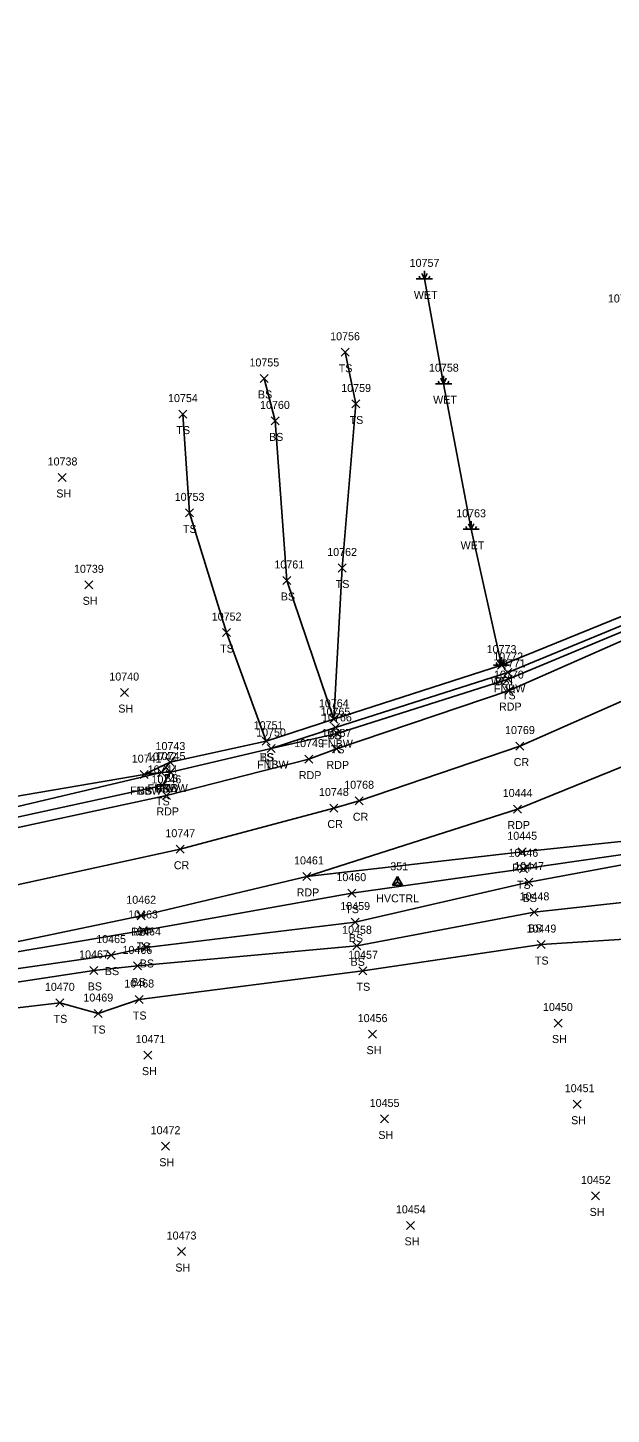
# Model space of a CAD drawing. Extents: x 1475671 to 1477951, y 592661 to 593821.
# Drawn here: x 1476339 to 1476484.8, y 592897.6 to 593244.1 of the extents above; entities that cross this region are included whole.
import ezdxf

# ---------------------------------------------------------------- set-up
doc = ezdxf.new("R2010")
doc.units = 0
for name, color, linetype in [('C_A', 7, 'Continuous'), ('C_I', 7, 'Continuous'), ('CPSM', 7, 'Continuous'), ('L_A', 7, 'Continuous'), ('L_I', 7, 'Continuous'), ('L_TIC', 7, 'Continuous'), ('LELB', 7, 'Continuous'), ('LFNC', 7, 'Continuous'), ('LWET', 7, 'Continuous'), ('P_A', 7, 'Continuous'), ('P_I', 7, 'Continuous'), ('P_TIC', 7, 'Continuous'), ('PET', 7, 'Continuous'), ('PRC', 7, 'Continuous')]:
    doc.layers.add(name, color=color, linetype=linetype)

msp = doc.modelspace()

# ---------------------------------------------------------------- linework, layer by layer
at = {"layer": 'CPSM'}
for p, q in [((1476430.13, 593029.85), (1476431.38, 593032.02)), ((1476432.63, 593029.85), (1476431.38, 593032.02)), ((1476431.38, 593030.57), (1476431.38, 593032.02)), ((1476430.13, 593029.85), (1476431.38, 593030.57)), ((1476430.13, 593029.85), (1476432.63, 593029.85)), ((1476431.38, 593030.57), (1476431.38, 593030.57)), ((1476431.38, 593030.57), (1476432.63, 593029.85))]:
    msp.add_line(p, q, dxfattribs=at)
at = {"layer": 'L_TIC'}
for points in [[(1476417.29, 593162.03), (1476419.29, 593164.03)], [(1476419.29, 593162.03), (1476417.29, 593164.03)], [(1476397.07, 593155.49), (1476399.07, 593157.49)], [(1476399.07, 593155.49), (1476397.07, 593157.49)], [(1476420.01, 593149.11), (1476422.01, 593151.11)], [(1476422.01, 593149.11), (1476420.01, 593151.11)], [(1476376.72, 593146.58), (1476378.72, 593148.58)], [(1476378.72, 593146.58), (1476376.72, 593148.58)], [(1476399.84, 593144.88), (1476401.84, 593146.88)], [(1476401.84, 593144.88), (1476399.84, 593146.88)], [(1476346.63, 593130.74), (1476348.63, 593132.74)], [(1476348.63, 593130.74), (1476346.63, 593132.74)], [(1476378.38, 593121.89), (1476380.38, 593123.89)], [(1476380.38, 593121.89), (1476378.38, 593123.89)], [(1476416.54, 593108.12), (1476418.54, 593110.12)], [(1476418.54, 593108.12), (1476416.54, 593110.12)], [(1476353.22, 593103.92), (1476355.22, 593105.92)], [(1476355.22, 593103.92), (1476353.22, 593105.92)], [(1476402.77, 593105), (1476404.77, 593107)], [(1476404.77, 593105), (1476402.77, 593107)], [(1476387.64, 593091.98), (1476389.64, 593093.98)], [(1476389.64, 593091.98), (1476387.64, 593093.98)], [(1476456.34, 593083.84), (1476458.34, 593085.84)], [(1476458.34, 593083.84), (1476456.34, 593085.84)], [(1476457.99, 593082.01), (1476459.99, 593084.01)], [(1476459.99, 593082.01), (1476457.99, 593084.01)], [(1476458.07, 593080.3), (1476460.07, 593082.3)], [(1476460.07, 593080.3), (1476458.07, 593082.3)], [(1476362.14, 593076.99), (1476364.14, 593078.99)], [(1476364.14, 593076.99), (1476362.14, 593078.99)], [(1476414.47, 593070.31), (1476416.47, 593072.31)], [(1476416.47, 593070.31), (1476414.47, 593072.31)], [(1476414.47, 593070.31), (1476416.47, 593072.31)], [(1476416.47, 593070.31), (1476414.47, 593072.31)], [(1476414.47, 593070.31), (1476416.47, 593072.31)], [(1476416.47, 593070.31), (1476414.47, 593072.31)], [(1476414.89, 593068.22), (1476416.89, 593070.22)], [(1476416.89, 593068.22), (1476414.89, 593070.22)], [(1476397.56, 593064.83), (1476399.56, 593066.83)], [(1476399.56, 593064.83), (1476397.56, 593066.83)], [(1476397.56, 593064.83), (1476399.56, 593066.83)], [(1476399.56, 593064.83), (1476397.56, 593066.83)], [(1476415.3, 593066.79), (1476417.3, 593068.79)], [(1476417.3, 593066.79), (1476415.3, 593068.79)], [(1476398.83, 593063.01), (1476400.83, 593065.01)], [(1476400.83, 593063.01), (1476398.83, 593065.01)], [(1476398.83, 593063.01), (1476400.83, 593065.01)], [(1476400.83, 593063.01), (1476398.83, 593065.01)], [(1476371.45, 593057.02), (1476373.45, 593059.02)], [(1476373.45, 593057.02), (1476371.45, 593059.02)], [(1476371.45, 593057.02), (1476373.45, 593059.02)], [(1476373.45, 593057.02), (1476371.45, 593059.02)], [(1476373.59, 593059.62), (1476375.59, 593061.62)], [(1476375.59, 593059.62), (1476373.59, 593061.62)], [(1476373.59, 593059.62), (1476375.59, 593061.62)], [(1476375.59, 593059.62), (1476373.59, 593061.62)], [(1476373.63, 593057.12), (1476375.63, 593059.12)], [(1476375.63, 593057.12), (1476373.63, 593059.12)], [(1476373.63, 593057.12), (1476375.63, 593059.12)], [(1476375.63, 593057.12), (1476373.63, 593059.12)], [(1476367.09, 593056.49), (1476369.09, 593058.49)], [(1476369.09, 593056.49), (1476367.09, 593058.49)], [(1476367.09, 593056.49), (1476369.09, 593058.49)], [(1476369.09, 593056.49), (1476367.09, 593058.49)], [(1476371.64, 593053.79), (1476373.64, 593055.79)], [(1476373.64, 593053.79), (1476371.64, 593055.79)], [(1476461.84, 593032.95), (1476463.84, 593034.95)], [(1476463.84, 593032.95), (1476461.84, 593034.95)], [(1476463.22, 593029.64), (1476465.22, 593031.64)], [(1476465.22, 593029.64), (1476463.22, 593031.64)], [(1476418.94, 593026.86), (1476420.94, 593028.86)], [(1476420.94, 593026.86), (1476418.94, 593028.86)], [(1476419.77, 593019.64), (1476421.77, 593021.64)], [(1476421.77, 593019.64), (1476419.77, 593021.64)], [(1476464.56, 593022.07), (1476466.56, 593024.07)], [(1476466.56, 593022.07), (1476464.56, 593024.07)], [(1476366.81, 593017.54), (1476368.81, 593019.54)], [(1476368.81, 593017.54), (1476366.81, 593019.54)], [(1476367.55, 593013.29), (1476369.55, 593015.29)], [(1476369.55, 593013.29), (1476367.55, 593015.29)], [(1476420.22, 593013.7), (1476422.22, 593015.7)], [(1476422.22, 593013.7), (1476420.22, 593015.7)], [(1476466.31, 593014.01), (1476468.31, 593016.01)], [(1476468.31, 593014.01), (1476466.31, 593016.01)], [(1476358.82, 593011.38), (1476360.82, 593013.38)], [(1476360.82, 593011.38), (1476358.82, 593013.38)], [(1476365.44, 593008.67), (1476367.44, 593010.67)], [(1476367.44, 593008.67), (1476365.44, 593010.67)], [(1476354.54, 593007.55), (1476356.54, 593009.55)], [(1476356.54, 593007.55), (1476354.54, 593009.55)], [(1476421.73, 593007.46), (1476423.73, 593009.46)], [(1476423.73, 593007.46), (1476421.73, 593009.46)], [(1476346.04, 592999.45), (1476348.04, 593001.45)], [(1476348.04, 592999.45), (1476346.04, 593001.45)], [(1476365.85, 593000.28), (1476367.85, 593002.28)], [(1476367.85, 593000.28), (1476365.85, 593002.28)], [(1476355.63, 592996.77), (1476357.63, 592998.77)], [(1476357.63, 592996.77), (1476355.63, 592998.77)], [(1476424.16, 592991.63), (1476426.16, 592993.63)], [(1476426.16, 592991.63), (1476424.16, 592993.63)], [(1476470.49, 592994.41), (1476472.49, 592996.41)], [(1476472.49, 592994.41), (1476470.49, 592996.41)], [(1476368.04, 592986.39), (1476370.04, 592988.39)], [(1476370.04, 592986.39), (1476368.04, 592988.39)], [(1476475.28, 592974.12), (1476477.28, 592976.12)], [(1476477.28, 592974.12), (1476475.28, 592976.12)], [(1476427.11, 592970.43), (1476429.11, 592972.43)], [(1476429.11, 592970.43), (1476427.11, 592972.43)], [(1476372.38, 592963.62), (1476374.38, 592965.62)], [(1476374.38, 592963.62), (1476372.38, 592965.62)], [(1476479.9, 592951.2), (1476481.9, 592953.2)], [(1476481.9, 592951.2), (1476479.9, 592953.2)], [(1476433.66, 592943.84), (1476435.66, 592945.84)], [(1476435.66, 592943.84), (1476433.66, 592945.84)], [(1476376.38, 592937.3), (1476378.38, 592939.3)], [(1476378.38, 592937.3), (1476376.38, 592939.3)]]:
    msp.add_lwpolyline(points, dxfattribs=at)
at = {"layer": 'LELB'}
for points in [[(1476418.29, 593163.03), (1476421.01, 593150.11), (1476417.54, 593109.12), (1476415.47, 593071.31)], [(1476398.07, 593156.49), (1476400.84, 593145.88), (1476403.77, 593106), (1476415.47, 593071.31)], [(1476398.56, 593065.83), (1476388.64, 593092.98), (1476379.38, 593122.89), (1476377.72, 593147.58)], [(1476399.83, 593064.01), (1476416.3, 593067.79), (1476459.07, 593081.3), (1476500.05, 593098.39), (1476506.4, 593103.47)], [(1475681.97, 592926.29), (1475693.99, 592930.92), (1475717.71, 592935.95), (1475764.49, 592948.74), (1475792.84, 592955.38), (1475826.76, 592965.2), (1475839.14, 592967.57), (1475847.44, 592968.45), (1475896, 592975.83), (1475948.75, 592985.5), (1475992.67, 592993.57), (1476057.44, 593003.96), (1476113.1, 593013.57), (1476163.64, 593021.28), (1476215.98, 593029.82), (1476272.69, 593037.85), (1476322.72, 593046.24), (1476372.45, 593058.02), (1476374.59, 593060.62), (1476398.56, 593065.83), (1476415.47, 593071.31), (1476457.34, 593084.84)], [(1476656.72, 593061.12), (1476648.18, 593059.88), (1476630.02, 593056.59), (1476594.66, 593048.99), (1476557.23, 593045.74), (1476521.08, 593042.35), (1476462.84, 593033.95), (1476419.94, 593027.86), (1476367.81, 593018.54), (1476319.05, 593010.3), (1476266.9, 593001.04), (1476164.01, 592984.31)], [(1476368.09, 593057.49), (1476374.59, 593060.62)], [(1475681.68, 592929.89), (1475693.99, 592930.92), (1475717.95, 592934.41), (1475766.45, 592946.03), (1475793.6, 592952.64), (1475827.75, 592961.96), (1475839.66, 592963.32), (1475897.61, 592972.89), (1475949.51, 592982.21), (1475996.32, 592990.67), (1476057.58, 593001.03), (1476113.5, 593010.46), (1476164.33, 593018.66), (1476216.45, 593027.16), (1476273.17, 593035.57), (1476322.97, 593043.9), (1476372.64, 593054.79), (1476374.63, 593058.12)], [(1476521.14, 593041.18), (1476464.22, 593030.64), (1476420.77, 593020.64), (1476368.55, 593014.29), (1476359.82, 593012.38), (1476319.88, 593006.6), (1476267.05, 592998.99), (1476216.33, 592991.85), (1476164.01, 592984.31), (1476119.67, 592976.43), (1476101.12, 592973.12), (1476050.25, 592964.51), (1475994.64, 592956.24), (1475948.73, 592947.98), (1475899.49, 592939.5), (1475855.9, 592931.1), (1475802.57, 592920.15), (1475791.75, 592916.74), (1475792.51, 592914.78)], [(1476534.65, 593028.56), (1476525.69, 593019.5), (1476511.54, 593017.85), (1476467.31, 593015.01), (1476422.73, 593008.46), (1476366.85, 593001.28), (1476356.63, 592997.77), (1476347.04, 593000.45), (1476320.8, 592997.35), (1476267.98, 592990.13), (1476216.9, 592984.46), (1476165.76, 592976.73), (1476117.9, 592968.73), (1476100.74, 592966.91), (1476051.72, 592958.25), (1475996.01, 592950.36), (1475948.39, 592939), (1475900.82, 592931.75), (1475857.92, 592923.91), (1475803.59, 592912.34), (1475790.59, 592904.71)], [(1476511.04, 593028.14), (1476465.56, 593023.07), (1476421.22, 593014.7), (1476366.44, 593009.67), (1476355.54, 593008.55), (1476320.37, 593003.18), (1476267.54, 592995.9), (1476216.93, 592987.92), (1476164.84, 592980.53), (1476118, 592971.7), (1476100.88, 592970.48), (1476050.95, 592961.21), (1475995.34, 592954.17), (1475949.24, 592944.73), (1475901.01, 592937.79), (1475856.17, 592929.37), (1475802.39, 592917.73), (1475792.51, 592914.78)]]:
    msp.add_lwpolyline(points, dxfattribs=at)
at = {"layer": 'LFNC'}
msp.add_lwpolyline([(1475680.63, 592937.28), (1475715.61, 592943.34), (1475763.84, 592955.14), (1475791.92, 592961.08), (1475824.89, 592967.76), (1475839.13, 592970.46), (1475847.47, 592971.97), (1475895.02, 592980.45), (1475948.31, 592989.25), (1475993.78, 592996.67), (1476056.99, 593006.94), (1476113.81, 593016.03), (1476164.23, 593025.08), (1476215.07, 593032.59), (1476272.43, 593042.08), (1476322.23, 593049.67), (1476368.09, 593057.49), (1476372.45, 593058.02), (1476374.63, 593058.12), (1476399.83, 593064.01), (1476415.89, 593069.22), (1476458.99, 593083.01), (1476499.73, 593099.84)], dxfattribs=at)
at = {"layer": 'LWET'}
for p, q in [((1476440.09, 593181.37), (1476436.09, 593181.37)), ((1476437.09, 593181.37), (1476436.76, 593182.03)), ((1476438.09, 593181.37), (1476437.43, 593182.7)), ((1476438.09, 593181.37), (1476438.09, 593183.37)), ((1476438.09, 593181.37), (1476438.76, 593182.7)), ((1476439.09, 593181.37), (1476439.43, 593182.03)), ((1476442.92, 593155.18), (1476442.25, 593156.52)), ((1476442.92, 593155.18), (1476442.92, 593157.18)), ((1476442.92, 593155.18), (1476443.58, 593156.52)), ((1476444.92, 593155.18), (1476440.92, 593155.18)), ((1476441.92, 593155.18), (1476441.58, 593155.85)), ((1476443.92, 593155.18), (1476444.25, 593155.85)), ((1476451.77, 593118.79), (1476447.77, 593118.79)), ((1476448.77, 593118.79), (1476448.44, 593119.46)), ((1476449.77, 593118.79), (1476449.11, 593120.13)), ((1476449.77, 593118.79), (1476449.77, 593120.79)), ((1476449.77, 593118.79), (1476450.44, 593120.13)), ((1476450.77, 593118.79), (1476451.11, 593119.46)), ((1476457.34, 593084.84), (1476457.34, 593086.84)), ((1476459.34, 593084.84), (1476455.34, 593084.84)), ((1476456.34, 593084.84), (1476456, 593085.5)), ((1476457.34, 593084.84), (1476456.67, 593086.17)), ((1476457.34, 593084.84), (1476458, 593086.17)), ((1476458.34, 593084.84), (1476458.67, 593085.5))]:
    msp.add_line(p, q, dxfattribs=at)
msp.add_lwpolyline([(1476438.09, 593181.37), (1476442.92, 593155.18), (1476449.77, 593118.79), (1476457.34, 593084.84), (1476498.59, 593101.6), (1476489.99, 593126.57), (1476487.68, 593172.48), (1476489.56, 593212.3), (1476496.66, 593244.14)], dxfattribs=at)
at = {"layer": 'P_TIC'}
for points in [[(1476458.25, 593077.48), (1476460.25, 593079.48)], [(1476460.25, 593077.48), (1476458.25, 593079.48)], [(1476415.16, 593062.9), (1476417.16, 593064.9)], [(1476417.16, 593062.9), (1476415.16, 593064.9)], [(1476460.98, 593063.62), (1476462.98, 593065.62)], [(1476462.98, 593063.62), (1476460.98, 593065.62)], [(1476408.24, 593060.35), (1476410.24, 593062.35)], [(1476410.24, 593060.35), (1476408.24, 593062.35)], [(1476372.65, 593051.29), (1476374.65, 593053.29)], [(1476374.65, 593051.29), (1476372.65, 593053.29)], [(1476414.44, 593048.14), (1476416.44, 593050.14)], [(1476416.44, 593048.14), (1476414.44, 593050.14)], [(1476420.8, 593049.95), (1476422.8, 593051.95)], [(1476422.8, 593049.95), (1476420.8, 593051.95)], [(1476460.35, 593047.89), (1476462.35, 593049.89)], [(1476462.35, 593047.89), (1476460.35, 593049.89)], [(1476376.06, 593037.84), (1476378.06, 593039.84)], [(1476378.06, 593037.84), (1476376.06, 593039.84)], [(1476461.5, 593037.2), (1476463.5, 593039.2)], [(1476463.5, 593037.2), (1476461.5, 593039.2)], [(1476407.69, 593031.05), (1476409.69, 593033.05)], [(1476409.69, 593031.05), (1476407.69, 593033.05)], [(1476407.69, 593031.05), (1476409.69, 593033.05)], [(1476409.69, 593031.05), (1476407.69, 593033.05)], [(1476366.34, 593021.2), (1476368.34, 593023.2)], [(1476368.34, 593021.2), (1476366.34, 593023.2)]]:
    msp.add_lwpolyline(points, dxfattribs=at)
at = {"layer": 'PET'}
for points in [[(1475682.06, 592924.71), (1475717.58, 592931.68), (1475766.32, 592943.31), (1475794.98, 592949.79), (1475825.77, 592956.33), (1475844.1, 592960.26), (1475899.54, 592970.95), (1475949.72, 592980.21), (1475996.45, 592988.43), (1476057.84, 592998.4), (1476110.05, 593006.96), (1476164.18, 593015.73), (1476216.75, 593023.76), (1476273.83, 593032.32), (1476323.32, 593041.42), (1476373.65, 593052.29), (1476409.24, 593061.35), (1476416.16, 593063.9), (1476459.25, 593078.48), (1476508.39, 593100.17)], [(1476493.61, 593061.9), (1476461.35, 593048.89), (1476408.69, 593032.05)], [(1476521.33, 593044.37), (1476462.5, 593038.2), (1476408.69, 593032.05), (1476367.34, 593022.2), (1476318.64, 593012.07), (1476266.69, 593003.36), (1476216.58, 592995.35), (1476163.86, 592987.33), (1476119.65, 592980.05), (1476101.05, 592977.22), (1476048.95, 592968.83), (1475997.04, 592960.32), (1475947.8, 592951.63), (1475898.72, 592942.8), (1475855.26, 592933.74), (1475801.94, 592923.33), (1475788.88, 592919.68), (1475771.17, 592916.5), (1475722.69, 592905.51), (1475685.82, 592897.63)]]:
    msp.add_lwpolyline(points, dxfattribs=at)
at = {"layer": 'PRC'}
msp.add_lwpolyline([(1475683.62, 592911.01), (1475719.65, 592918.7), (1475759.33, 592927.39), (1475790.86, 592934.39), (1475834.03, 592943.87), (1475901.67, 592957.18), (1475953.57, 592967.02), (1476000.12, 592975.16), (1476059.54, 592984.65), (1476113.3, 592993.58), (1476166.39, 593001.74), (1476218.93, 593009.6), (1476277, 593018.86), (1476325.59, 593027.6), (1476377.06, 593038.84), (1476415.44, 593049.14), (1476421.8, 593050.95), (1476461.98, 593064.62), (1476520.7, 593090.52)], dxfattribs=at)

# ---------------------------------------------------------------- texts
at = {"layer": 'C_A'}
msp.add_text('HVCTRL', height=2, dxfattribs=at).set_placement((1476426.07, 593025.57))
at = {"layer": 'C_I'}
msp.add_text('351', height=2, dxfattribs=at).set_placement((1476429.58, 593033.57))
at = {"layer": 'L_A'}
for s, p in [('WET', (1476435.47, 593176.37)), ('TS', (1476416.7, 593158.03)), ('BS', (1476396.51, 593151.49)), ('WET', (1476440.29, 593150.18)), ('TS', (1476419.42, 593145.11)), ('TS', (1476376.13, 593142.58)), ('BS', (1476399.28, 593140.88)), ('SH', (1476346.12, 593126.74)), ('TS', (1476377.79, 593117.89)), ('WET', (1476447.15, 593113.79)), ('TS', (1476415.95, 593104.12)), ('SH', (1476352.71, 593099.92)), ('BS', (1476402.22, 593101)), ('TS', (1476387.05, 593087.98)), ('WET', (1476454.71, 593079.84)), ('FNBW', (1476455.47, 593078.01)), ('BS', (1476455.78, 593079.84)), ('TS', (1476457.48, 593076.3)), ('SH', (1476361.62, 593072.99)), ('FNBW', (1476412.36, 593064.22)), ('TS', (1476413.88, 593066.31)), ('BS', (1476413.91, 593066.31)), ('BS', (1476413.91, 593066.31)), ('TS', (1476396.96, 593060.83)), ('BS', (1476397, 593060.83)), ('TS', (1476414.71, 593062.79)), ('FNBW', (1476396.3, 593059.01)), ('TS', (1476398.24, 593059.01)), ('BS', (1476373.03, 593055.62)), ('BS', (1476373.03, 593055.62)), ('FNBW', (1476364.56, 593052.49)), ('BS', (1476366.53, 593052.49)), ('FNBW', (1476368.92, 593053.02)), ('BS', (1476370.89, 593053.02)), ('FNBW', (1476371.11, 593053.12)), ('TS', (1476373.04, 593053.12)), ('TS', (1476371.05, 593049.79)), ('TS', (1476461.25, 593028.95)), ('TS', (1476418.35, 593022.86)), ('BS', (1476462.66, 593025.64)), ('BS', (1476419.21, 593015.64)), ('BS', (1476464, 593018.07)), ('TS', (1476366.21, 593013.54)), ('BS', (1476366.99, 593009.29)), ('BS', (1476419.66, 593009.7)), ('TS', (1476465.72, 593010.01)), ('BS', (1476358.26, 593007.38)), ('BS', (1476353.98, 593003.55)), ('BS', (1476364.88, 593004.67)), ('TS', (1476421.14, 593003.46)), ('TS', (1476345.45, 592995.45)), ('TS', (1476365.26, 592996.28)), ('TS', (1476355.04, 592992.77)), ('SH', (1476423.65, 592987.63)), ('SH', (1476469.98, 592990.41)), ('SH', (1476367.53, 592982.39)), ('SH', (1476474.77, 592970.12)), ('SH', (1476426.6, 592966.43)), ('SH', (1476371.87, 592959.62)), ('SH', (1476479.39, 592947.2)), ('SH', (1476433.15, 592939.84)), ('SH', (1476375.87, 592933.3))]:
    msp.add_text(s, height=2, dxfattribs=at).set_placement(p)
at = {"layer": 'L_I'}
for s, p in [('10757', (1476434.42, 593184.37)), ('10796', (1476483.95, 593175.48)), ('10756', (1476414.56, 593166.03)), ('10755', (1476394.4, 593159.49)), ('10758', (1476439.25, 593158.18)), ('10754', (1476374.05, 593150.58)), ('10759', (1476417.33, 593153.11)), ('10760', (1476397.04, 593148.88)), ('10738', (1476343.96, 593134.74)), ('10753', (1476375.71, 593125.89)), ('10763', (1476446.06, 593121.79)), ('10761', (1476400.63, 593109)), ('10762', (1476413.82, 593112.12)), ('10739', (1476350.55, 593107.92)), ('10752', (1476384.97, 593095.98)), ('10773', (1476453.67, 593087.84)), ('10773', (1476453.67, 593087.84)), ('10772', (1476455.32, 593086.01)), ('10771', (1476455.97, 593084.3)), ('10740', (1476359.38, 593080.99)), ('10764', (1476411.75, 593074.31)), ('10764', (1476411.75, 593074.31)), ('10764', (1476411.75, 593074.31)), ('10765', (1476412.17, 593072.22)), ('10766', (1476412.53, 593070.79)), ('10751', (1476395.45, 593068.83)), ('10751', (1476395.45, 593068.83)), ('10750', (1476396.07, 593067.01)), ('10750', (1476396.07, 593067.01)), ('10741', (1476364.98, 593060.49)), ('10741', (1476364.98, 593060.49)), ('10742', (1476368.78, 593061.02)), ('10742', (1476368.78, 593061.02)), ('10743', (1476370.92, 593063.62)), ('10743', (1476370.92, 593063.62)), ('10745', (1476370.96, 593061.12)), ('10745', (1476370.96, 593061.12)), ('10744', (1476368.97, 593057.79)), ('10446', (1476459.12, 593036.95)), ('10447', (1476460.55, 593033.64)), ('10460', (1476416.13, 593030.86)), ('10448', (1476461.89, 593026.07)), ('10459', (1476417.09, 593023.64)), ('10463', (1476364.09, 593021.54)), ('10465', (1476356.1, 593015.38)), ('10464', (1476364.83, 593017.29)), ('10458', (1476417.55, 593017.7)), ('10449', (1476463.63, 593018.01)), ('10466', (1476362.67, 593012.67)), ('10467', (1476351.83, 593011.55)), ('10457', (1476419.06, 593011.46)), ('10470', (1476343.29, 593003.45)), ('10468', (1476363.13, 593004.28)), ('10469', (1476352.9, 593000.77)), ('10450', (1476467.74, 592998.41)), ('10456', (1476421.44, 592995.63)), ('10471', (1476365.94, 592990.39)), ('10451', (1476473.18, 592978.12)), ('10455', (1476424.44, 592974.43)), ('10472', (1476369.71, 592967.62)), ('10452', (1476477.23, 592955.2)), ('10454', (1476430.99, 592947.84)), ('10473', (1476373.71, 592941.3))]:
    msp.add_text(s, height=2, dxfattribs=at).set_placement(p)
at = {"layer": 'P_A'}
for s, p in [('RDP', (1476456.74, 593073.48)), ('RDP', (1476413.65, 593058.9)), ('CR', (1476460.41, 593059.62)), ('RDP', (1476406.73, 593056.35)), ('RDP', (1476371.14, 593047.29)), ('CR', (1476413.87, 593044.14)), ('CR', (1476420.23, 593045.95)), ('RDP', (1476458.84, 593043.89)), ('CR', (1476375.5, 593033.84)), ('RDP', (1476459.99, 593033.2)), ('RDP', (1476406.18, 593027.05)), ('RDP', (1476406.18, 593027.05)), ('RDP', (1476364.82, 593017.2))]:
    msp.add_text(s, height=2, dxfattribs=at).set_placement(p)
at = {"layer": 'P_I'}
for s, p in [('10770', (1476455.5, 593081.48)), ('10769', (1476458.26, 593067.62)), ('10749', (1476405.56, 593064.35)), ('10767', (1476412.44, 593066.9)), ('10746', (1476369.92, 593055.29)), ('10768', (1476418.08, 593053.95)), ('10748', (1476411.77, 593052.14)), ('10444', (1476457.68, 593051.89)), ('10747', (1476373.39, 593041.84)), ('10445', (1476458.83, 593041.2)), ('10461', (1476405.54, 593035.05)), ('10461', (1476405.54, 593035.05)), ('10462', (1476363.62, 593025.2))]:
    msp.add_text(s, height=2, dxfattribs=at).set_placement(p)

doc.saveas('drawing.dxf')
